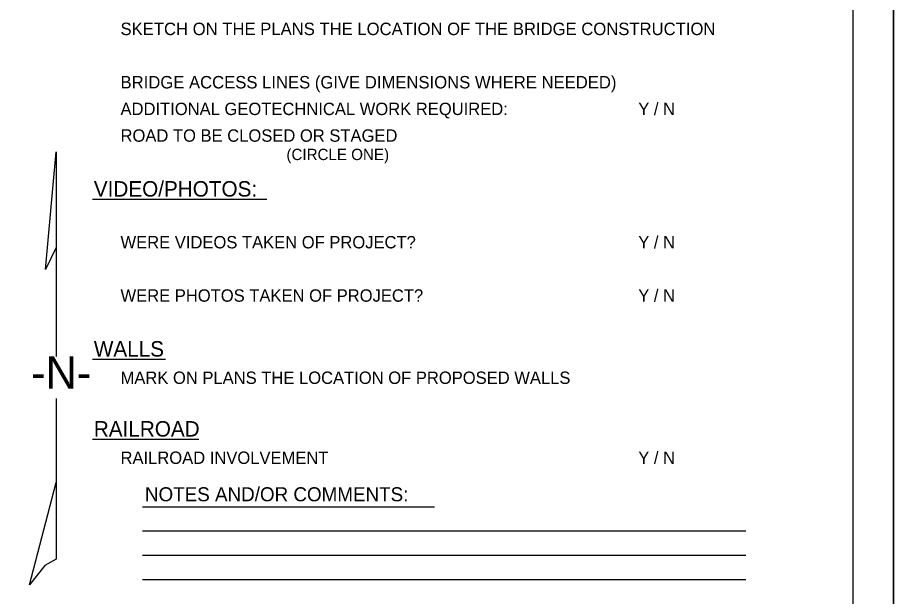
# Model space of a CAD drawing. Extents: x 160093 to 164626, y 177093 to 182727.
# Drawn here: x 162314 to 162856, y 178563 to 178921 of the extents above; entities that cross this region are included whole.
import ezdxf

# ---------------------------------------------------------------- set-up
doc = ezdxf.new("R2010")
doc.units = 0
for name, color, linetype in [('Level 11', 7, 'Continuous'), ('Level 38', 7, 'Continuous'), ('Level 40', 7, 'Continuous'), ('Level 42', 7, 'Continuous'), ('Level 43', 7, 'Continuous')]:
    doc.layers.add(name, color=color, linetype=linetype)

msp = doc.modelspace()

# ---------------------------------------------------------------- linework, layer by layer
at = {"layer": 'Level 11'}
for p, q in [((162331.83, 178765.25), (162338.49, 178838.04)), ((162338.49, 178838.04), (162338.49, 178778.77)), ((162338.49, 178778.77), (162331.83, 178765.25)), ((162338.49, 178778.77), (162338.49, 178737.68)), ((162338.49, 178737.68), (162338.49, 178711.48)), ((162338.49, 178685.32), (162338.49, 178633.52)), ((162322, 178570.05), (162338.49, 178633.52)), ((162338.49, 178633.52), (162338.49, 178625.68)), ((162338.49, 178625.68), (162338.49, 178585.99))]:
    msp.add_line(p, q, dxfattribs=at)
msp.add_lwpolyline([(162338.49, 178585.99), (162331.41, 178582.11), (162322, 178570.05)], dxfattribs=at)
at = {"layer": 'Level 38'}
for p, q in [((162831.14, 178230.28), (162831.14, 179280.28)), ((162360.94, 178808.76), (162468.73, 178808.76)), ((162360.94, 178709.76), (162405.91, 178709.76)), ((162360.94, 178660.26), (162426.6, 178660.26)), ((162391.77, 178618.47), (162572.28, 178618.47)), ((162391.77, 178618.47), (162403.46, 178618.47)), ((162391.77, 178618.47), (162503.71, 178618.47)), ((162391.77, 178603.47), (162764.94, 178603.47)), ((162391.77, 178588.47), (162764.94, 178588.47)), ((162391.77, 178573.47), (162764.94, 178573.47))]:
    msp.add_line(p, q, dxfattribs=at)
at = {"layer": 'Level 42'}
msp.add_lwpolyline([(161060.14, 179305.28), (162856.13, 179305.28), (162856.13, 178205.28), (161060.14, 178205.28)], close=True, dxfattribs=at)
at = {"layer": 'Level 43'}
msp.add_line((162856.04, 179305.28), (162856.04, 178205.28), dxfattribs=at)

# ---------------------------------------------------------------- texts
at = {"layer": 'Level 11'}
msp.add_text('-N-', height=20, dxfattribs=at).set_placement((162322.92, 178691.6))
at = {"layer": 'Level 40'}
for s, height, p in [('SKETCH ON THE PLANS THE LOCATION OF THE BRIDGE CONSTRUCTION  ', 7.7001, (162378.18, 178910.29)), ('BRIDGE ACCESS LINES (GIVE DIMENSIONS WHERE NEEDED)', 7.7001, (162378.18, 178877.29)), ('ADDITIONAL GEOTECHNICAL WORK REQUIRED:', 7.6561, (162378.18, 178860.81)), ('Y / N', 7.656, (162698.31, 178860.81)), ('ROAD TO BE CLOSED OR STAGED', 7.6561, (162378.18, 178844.31)), ('(CIRCLE ONE)', 7.0001, (162480.78, 178832.95)), ('VIDEO/PHOTOS:', 9.5701, (162361.68, 178810.36)), ('Y / N', 7.656, (162698.31, 178778.31)), ('WERE VIDEOS TAKEN OF PROJECT?', 7.6561, (162378.18, 178778.31)), ('WERE PHOTOS TAKEN OF PROJECT?', 7.6561, (162378.18, 178745.31)), ('Y / N', 7.656, (162698.31, 178745.31)), ('WALLS', 9.57, (162361.68, 178711.35)), ('MARK ON PLANS THE LOCATION OF PROPOSED WALLS', 7.6561, (162378.18, 178694.43)), ('RAILROAD', 9.57, (162361.68, 178661.85)), ('RAILROAD INVOLVEMENT', 7.6561, (162378.18, 178644.93)), ('Y / N', 7.656, (162698.31, 178644.93)), ('NOTES AND/OR COMMENTS:', 8.7001, (162393.29, 178621.8))]:
    msp.add_text(s, height=height, dxfattribs=at).set_placement(p)

doc.saveas('drawing.dxf')
